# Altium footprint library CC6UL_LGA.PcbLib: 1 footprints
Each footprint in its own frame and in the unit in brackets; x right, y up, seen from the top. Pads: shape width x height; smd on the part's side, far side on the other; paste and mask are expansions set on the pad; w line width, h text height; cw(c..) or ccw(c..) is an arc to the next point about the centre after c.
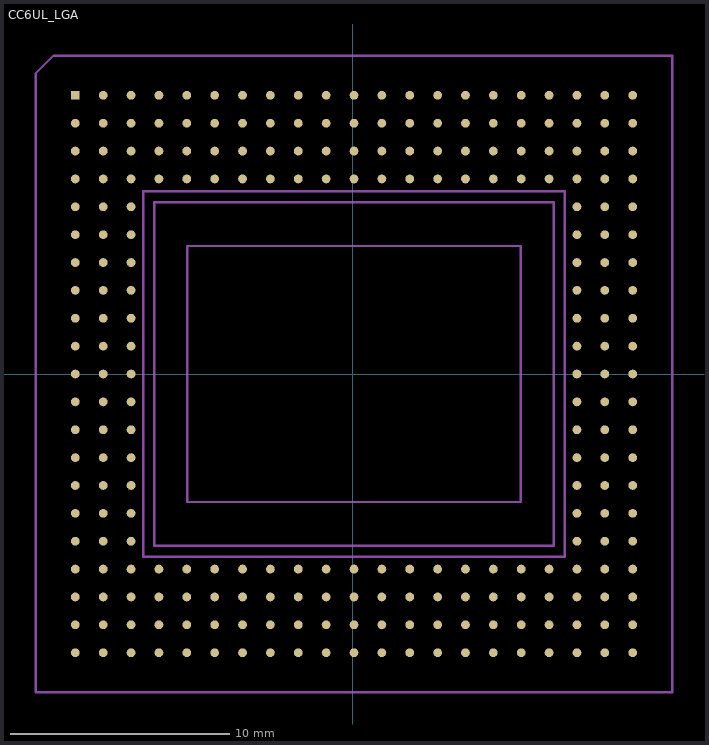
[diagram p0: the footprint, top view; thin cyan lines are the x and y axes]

## CC6UL_LGA [mm]
height 5
pads (246):
  rect 0.4x0.4 smd paste-0.4: A1(-12.64,12.7)
  round 0.4 smd mask+0.05: A2(-11.37,12.7) A3(-10.1,12.7) A4(-8.83,12.7) A5(-7.56,12.7) A6(-6.29,12.7) A7(-5.02,12.7) A8(-3.75,12.7) A9(-2.48,12.7) A10(-1.21,12.7) A11(0.06,12.7) A12(1.33,12.7) A13(2.6,12.7) A14(3.87,12.7) A15(5.14,12.7) A16(6.41,12.7) A17(7.68,12.7) A18(8.95,12.7) A19(10.22,12.7) A20(11.49,12.7) A21(12.76,12.7) AA1(-12.64,-12.7) AA2(-11.37,-12.7) AA3(-10.1,-12.7) AA4(-8.83,-12.7) AA5(-7.56,-12.7) AA6(-6.29,-12.7) AA7(-5.02,-12.7) AA8(-3.75,-12.7) AA9(-2.48,-12.7) AA10(-1.21,-12.7) AA11(0.06,-12.7) AA12(1.33,-12.7) AA13(2.6,-12.7) AA14(3.87,-12.7) AA15(5.14,-12.7) AA16(6.41,-12.7) AA17(7.68,-12.7) AA18(8.95,-12.7) AA19(10.22,-12.7) AA20(11.49,-12.7) AA21(12.76,-12.7) B1(-12.64,11.43) B2(-11.37,11.43) B3(-10.1,11.43) B4(-8.83,11.43) B5(-7.56,11.43) B6(-6.29,11.43) B7(-5.02,11.43) B8(-3.75,11.43) B9(-2.48,11.43) B10(-1.21,11.43) B11(0.06,11.43) B12(1.33,11.43) B13(2.6,11.43) B14(3.87,11.43) B15(5.14,11.43) B16(6.41,11.43) B17(7.68,11.43) B18(8.95,11.43) B19(10.22,11.43) B20(11.49,11.43) B21(12.76,11.43) C1(-12.64,10.16) C2(-11.37,10.16) C3(-10.1,10.16) C4(-8.83,10.16) C5(-7.56,10.16) C6(-6.29,10.16) C7(-5.02,10.16) C8(-3.75,10.16) C9(-2.48,10.16) C10(-1.21,10.16) C11(0.06,10.16) C12(1.33,10.16) C13(2.6,10.16) C14(3.87,10.16) C15(5.14,10.16) C16(6.41,10.16) C17(7.68,10.16) C18(8.95,10.16) C19(10.22,10.16) C20(11.49,10.16) C21(12.76,10.16) D1(-12.64,8.89) D2(-11.37,8.89) D3(-10.1,8.89) D4(-8.83,8.89) D5(-7.56,8.89) D6(-6.29,8.89) D7(-5.02,8.89) D8(-3.75,8.89) D9(-2.48,8.89) D10(-1.21,8.89) D11(0.06,8.89) D12(1.33,8.89) D13(2.6,8.89) D14(3.87,8.89) D15(5.14,8.89) D16(6.41,8.89) D17(7.68,8.89) D18(8.95,8.89) D19(10.22,8.89) D20(11.49,8.89) D21(12.76,8.89) E1(-12.64,7.62) E2(-11.37,7.62) E3(-10.1,7.62) E19(10.22,7.62) E20(11.49,7.62) E21(12.76,7.62) F1(-12.64,6.35) F2(-11.37,6.35) F3(-10.1,6.35) F19(10.22,6.35) F20(11.49,6.35) F21(12.76,6.35) G1(-12.64,5.08) G2(-11.37,5.08) G3(-10.1,5.08) G19(10.22,5.08) G20(11.49,5.08) G21(12.76,5.08) H1(-12.64,3.81) H2(-11.37,3.81) H3(-10.1,3.81) H19(10.22,3.81) H20(11.49,3.81) H21(12.76,3.81) J1(-12.64,2.54) J2(-11.37,2.54) J3(-10.1,2.54) J19(10.22,2.54) J20(11.49,2.54) J21(12.76,2.54) K1(-12.64,1.27) K2(-11.37,1.27) K3(-10.1,1.27) K19(10.22,1.27) K20(11.49,1.27) K21(12.76,1.27) L1(-12.64,0) L2(-11.37,0) L3(-10.1,0) L19(10.22,0) L20(11.49,0) L21(12.76,0) M1(-12.64,-1.27) M2(-11.37,-1.27) M3(-10.1,-1.27) M19(10.22,-1.27) M20(11.49,-1.27) M21(12.76,-1.27) N1(-12.64,-2.54) N2(-11.37,-2.54) N3(-10.1,-2.54) N19(10.22,-2.54) N20(11.49,-2.54) N21(12.76,-2.54) P1(-12.64,-3.81) P2(-11.37,-3.81) P3(-10.1,-3.81) P19(10.22,-3.81) P20(11.49,-3.81) P21(12.76,-3.81) R1(-12.64,-5.08) R2(-11.37,-5.08) R3(-10.1,-5.08) R19(10.22,-5.08) R20(11.49,-5.08) R21(12.76,-5.08) T1(-12.64,-6.35) T2(-11.37,-6.35) T3(-10.1,-6.35) T19(10.22,-6.35) T20(11.49,-6.35) T21(12.76,-6.35) U1(-12.64,-7.62) U2(-11.37,-7.62) U3(-10.1,-7.62) U19(10.22,-7.62) U20(11.49,-7.62) U21(12.76,-7.62) V1(-12.64,-8.89) V2(-11.37,-8.89) V3(-10.1,-8.89) V4(-8.83,-8.89) V5(-7.56,-8.89) V6(-6.29,-8.89) V7(-5.02,-8.89) V8(-3.75,-8.89) V9(-2.48,-8.89) V10(-1.21,-8.89) V11(0.06,-8.89) V12(1.33,-8.89) V13(2.6,-8.89) V14(3.87,-8.89) V15(5.14,-8.89) V16(6.41,-8.89) V17(7.68,-8.89) V18(8.95,-8.89) V19(10.22,-8.89) V20(11.49,-8.89) V21(12.76,-8.89) W1(-12.64,-10.16) W2(-11.37,-10.16) W3(-10.1,-10.16) W4(-8.83,-10.16) W5(-7.56,-10.16) W6(-6.29,-10.16) W7(-5.02,-10.16) W8(-3.75,-10.16) W9(-2.48,-10.16) W10(-1.21,-10.16) W11(0.06,-10.16) W12(1.33,-10.16) W13(2.6,-10.16) W14(3.87,-10.16) W15(5.14,-10.16) W16(6.41,-10.16) W17(7.68,-10.16) W18(8.95,-10.16) W19(10.22,-10.16) W20(11.49,-10.16) W21(12.76,-10.16) Y1(-12.64,-11.43) Y2(-11.37,-11.43) Y3(-10.1,-11.43) Y4(-8.83,-11.43) Y5(-7.56,-11.43) Y6(-6.29,-11.43) Y7(-5.02,-11.43) Y8(-3.75,-11.43) Y9(-2.48,-11.43) Y10(-1.21,-11.43) Y11(0.06,-11.43) Y12(1.33,-11.43) Y13(2.6,-11.43) Y14(3.87,-11.43) Y15(5.14,-11.43) Y16(6.41,-11.43) Y17(7.68,-11.43) Y18(8.95,-11.43) Y19(10.22,-11.43) Y20(11.49,-11.43) Y21(12.76,-11.43)
Mechanical 1:
  lines w0.102: -9.04,-7.83 9.16,-7.83 9.16,7.83 -9.04,7.83 -9.04,-7.82
Mechanical 2:
  lines w0.102: -9.54,-8.33 -9.54,8.33 9.66,8.33 9.66,-8.33 -9.54,-8.33 ; -7.54,-5.83 7.66,-5.83 7.66,5.83 -7.54,5.83 -7.54,-5.83
Mechanical 3:
  lines w0.102: -14.44,-14.5 14.56,-14.5 14.56,14.5 -13.64,14.5 -14.44,13.7 -14.44,-14.5
  text ".Designator" at -1.25,-0.5 h1
3D body "55001875_pcba_ccimx6ul_asm_04-27.stp": height 4.35, standoff 0, extent -14.44,-14.5 14.56,17.356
